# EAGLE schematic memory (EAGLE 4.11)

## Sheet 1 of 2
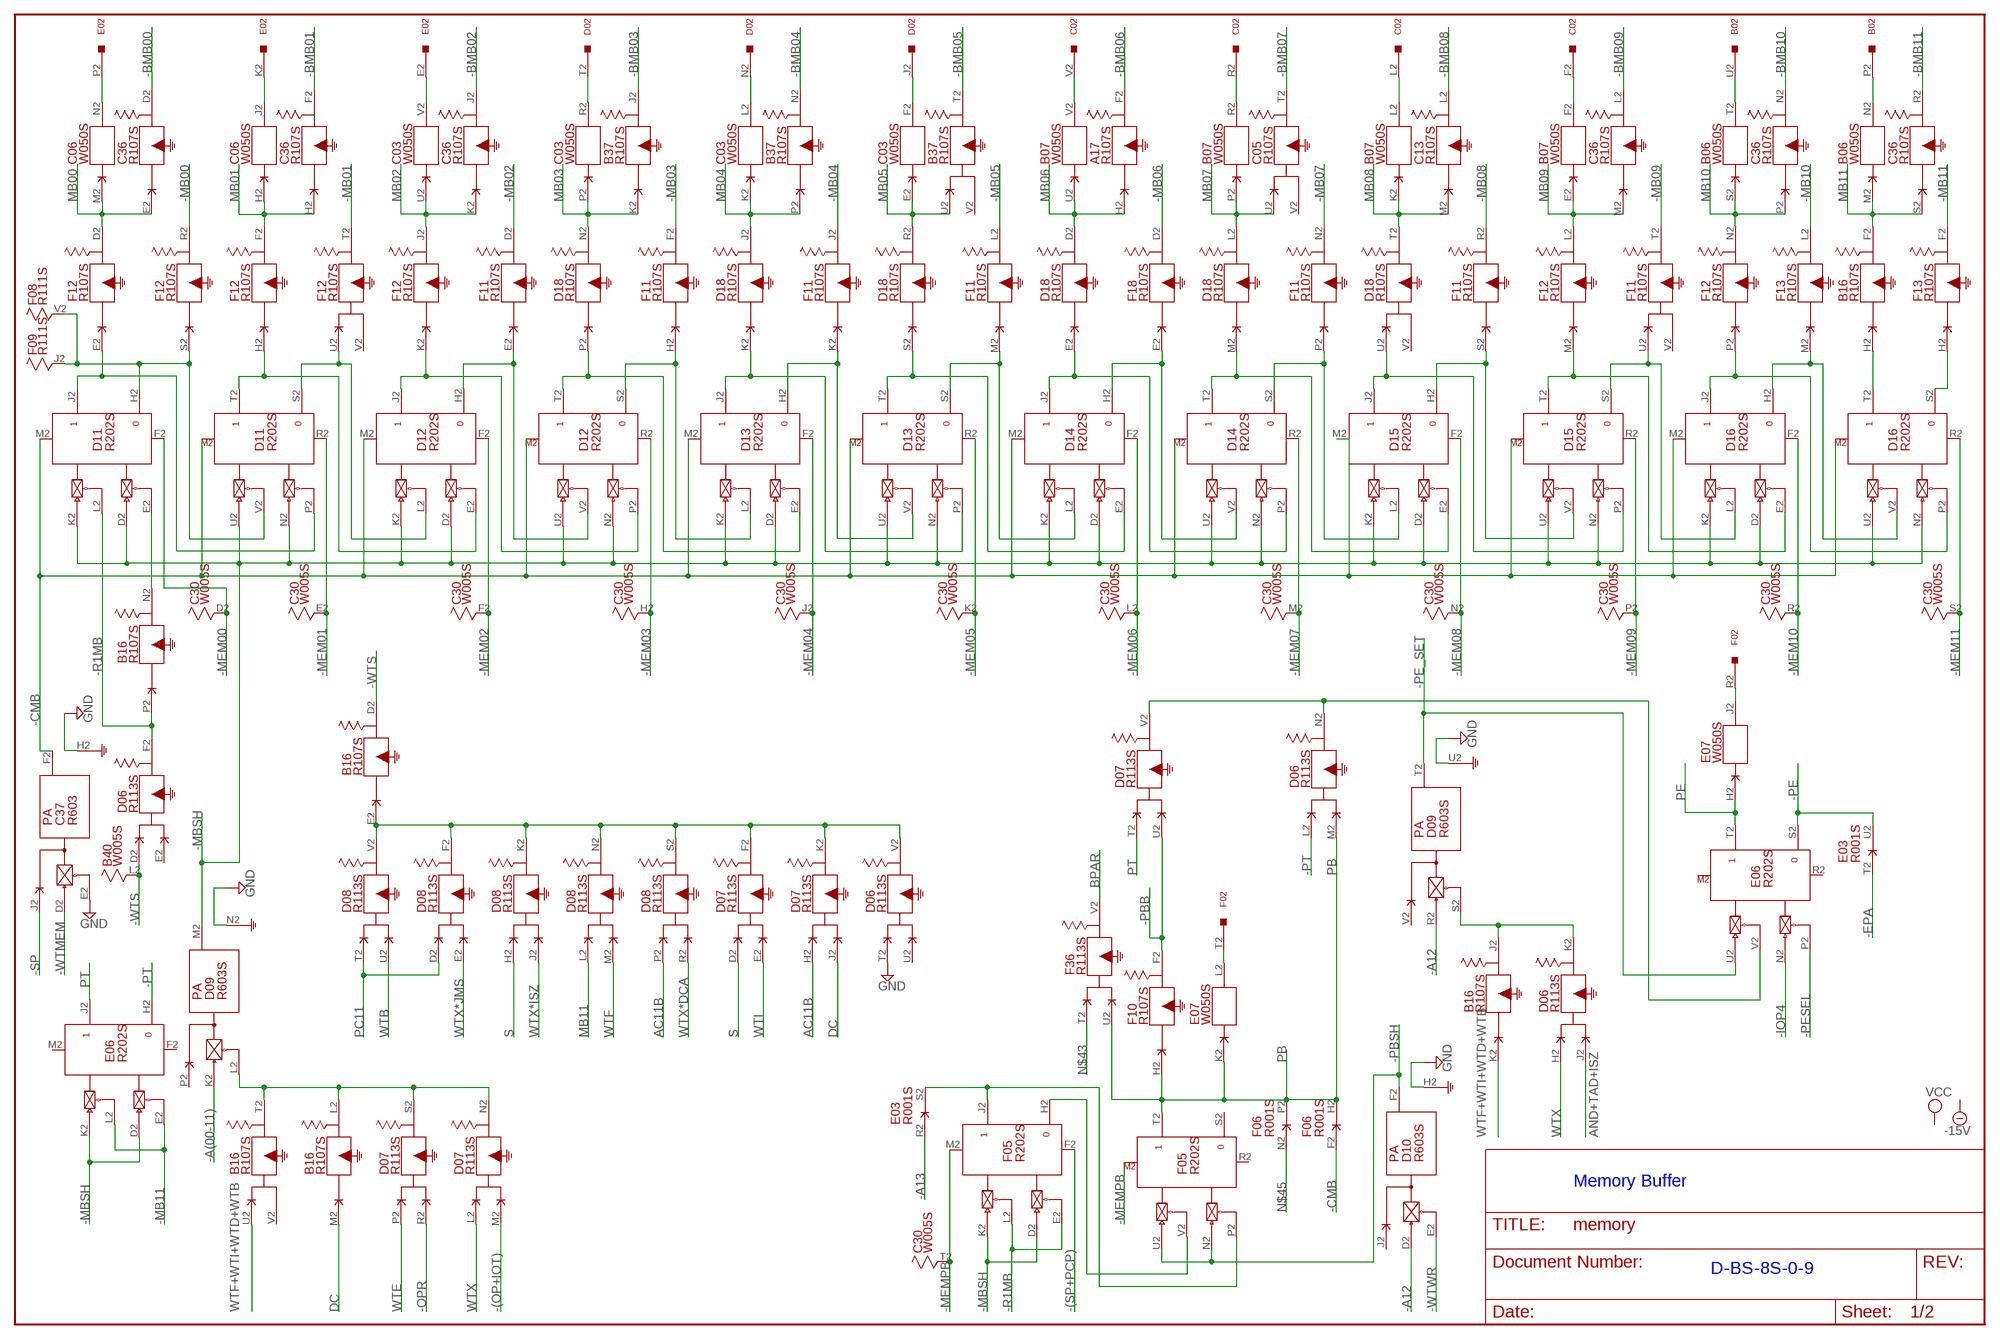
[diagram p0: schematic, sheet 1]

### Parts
A17  R107S  [H807S]
B02  W023S  [H807S]
B06  W050S  [H807S]
B07  W050S  [H807S]
B16  R107S  [H807S]
B37  R107S  [H807S]
B40  W005S  [H807S]
C02  W023S  [H807S]
C03  W050S  [H807S]
C05  R107S  [H807S]
C06  W050S  [H807S]
C13  R107S  [H807S]
C30  W005S  [H807S]
C36  R107S  [H807S]
C37  R603  [H807]
D02  W023S  [H807S]
D06  R113S  [H807S]
D07  R113S  [H807S]
D08  R113S  [H807S]
D09  R603S  [H807S]
D10  R603S  [H807S]
D11  R202S  [H807S]
D12  R202S  [H807S]
D13  R202S  [H807S]
D14  R202S  [H807S]
D15  R202S  [H807S]
D16  R202S  [H807S]
D18  R107S  [H807S]
E02  W023S  [H807S]
E03  R001S  [H807S]
E06  R202S  [H807S]
E07  W050S  [H807S]
F02  W023S  [H807S]
F05  R202S  [H807S]
F06  R001S  [H807S]
F08  R111S  [H807S]
F09  R111S  [H807S]
F10  R107S  [H807S]
F11  R107S  [H807S]
F12  R107S  [H807S]
F13  R107S  [H807S]
F18  R107S  [H807S]
F36  R113S  [H807S]

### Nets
-(OP+IOT): D07.M2(N:I$2)
-(SP+PCP): F05.F2(J:RESET)
-A12: D09.R2(T:PU0) D10.D2(F:PU0)
-A13: E03.R2(S:D)
-A(00-11): D09.K2(M:PU0)
-BMB00: C36.D2(D:O$1)
-BMB01: C36.F2(F:O$1)
-BMB02: C36.J2(J:O$1)
-BMB03: B37.J2(J:O$1)
-BMB04: B37.N2(N:O$1)
-BMB05: B37.T2(T:O$1)
-BMB06: A17.F2(F:O$1)
-BMB07: C05.T2(T:O$1)
-BMB08: C13.L2(L:O$1)
-BMB09: C36.L2(L:O$1)
-BMB10: C36.N2(N:O$1)
-BMB11: C36.R2(R:O$1)
-CMB: C37.F2(F:O) D11.M2(J:SET) D12.M2(J:SET) D13.M2(J:SET) D14.M2(J:SET) D15.M2(J:SET) D16.M2(J:SET) F06.F2(H:D)
-EPA: E03.T2(U:D)
-IOP4: E06.N2(T:PU0)
-MB00: F12.R2(R:O$1) ; also sheet 2
-MB01: F12.T2(T:O$1) ; also sheet 2
-MB02: F11.D2(D:O$1) ; also sheet 2
-MB03: F11.F2(F:O$1) ; also sheet 2
-MB04: F11.J2(J:O$1) ; also sheet 2
-MB05: F11.L2(L:O$1) ; also sheet 2
-MB06: F18.D2(D:O$1) ; also sheet 2
-MB07: F11.N2(N:O$1) ; also sheet 2
-MB08: F11.R2(R:O$1) ; also sheet 2
-MB09: F11.T2(T:O$1) ; also sheet 2
-MB10: F13.L2(L:O$1) ; also sheet 2
-MB11: E06.E2(J:EN0) E06.L2(J:EN1) F13.F2(F:O$1) ; also sheet 2
-MBSH: D09.M2(M:O) D11.D2(J:PU0) D11.K2(J:PU1) D11.N2(T:PU0) D11.U2(T:PU1) D12.D2(J:PU0) D12.K2(J:PU1) D12.N2(T:PU0) D12.U2(T:PU1) D13.D2(J:PU0) D13.K2(J:PU1) D13.N2(T:PU0) D13.U2(T:PU1) D14.D2(J:PU0) D14.K2(J:PU1) D14.N2(T:PU0) D14.U2(T:PU1) D15.D2(J:PU0) D15.K2(J:PU1) D15.N2(T:PU0) D15.U2(T:PU1) D16.D2(J:PU0) D16.K2(J:PU1) D16.N2(T:PU0) D16.U2(T:PU1) E06.D2(J:PU0) E06.K2(J:PU1) F05.D2(J:PU0) F05.K2(J:PU1)
-MEM00: C30.D2 D11.F2(J:RESET) ; also sheet 2
-MEM01: C30.E2 D11.R2(T:RESET) ; also sheet 2
-MEM02: C30.F2 D12.F2(J:RESET) ; also sheet 2
-MEM03: C30.H2 D12.R2(T:RESET) ; also sheet 2
-MEM04: C30.J2 D13.F2(J:RESET) ; also sheet 2
-MEM05: C30.K2 D13.R2(T:RESET) ; also sheet 2
-MEM06: C30.L2 D14.F2(J:RESET) ; also sheet 2
-MEM07: C30.M2 D14.R2(T:RESET) ; also sheet 2
-MEM08: C30.N2 D15.F2(J:RESET) ; also sheet 2
-MEM09: C30.P2 D15.R2(T:RESET) ; also sheet 2
-MEM10: C30.R2 D16.F2(J:RESET) ; also sheet 2
-MEM11: C30.S2 D16.R2(T:RESET) ; also sheet 2
-MEMPB: C30.T2 F05.M2(J:SET) ; also sheet 2
-OPR: D07.R2(S:I$2)
-PBB: D07.U2(V:I$2) F10.F2(F:O$1) ; also sheet 2
-PBSH: D10.F2(F:O) F05.N2(T:PU0) F05.U2(T:PU1)
-PE: E03.U2(U:E) E06.S2
-PE_SET: D09.T2(T:O) E06.U2(T:PU1)
-PESEL: E06.P2(T:EN0)
-PT: D06.L2(N:I$1) E06.H2
-R1MB: B16.P2(N:I$1) D06.F2(F:O$1) D11.L2(J:EN1) F05.E2(J:EN0) F05.L2(J:EN1)
-SP: C37.J2(F:I$1)
-WTMEM: C37.D2(F:PU0)
-WTS: B16.D2(D:O$1) B40.L2 D06.D2(F:I$1)
-WTWR: D10.E2(F:EN0)
AC11B: D07.H2(K:I$1) D08.P2(S:I$1)
AND+TAD+ISZ: D06.J2(K:I$2)
BPAR: F36.V2(V:O$1)
DC: B16.M2(L:I$1) D07.J2(K:I$2)
GND [Supply]: C37.E2(F:EN0) C37.H2(F:G) D06.T2(V:I$1) D09.N2(M:G) D09.U2(T:G) D10.H2(F:G) ; also sheet 2
MB00: C06.M2(N:I$1) C36.E2(D:I$1) F12.D2(D:O$1)
MB01: C06.H2(J:I$1) C36.H2(F:I$1) F12.F2(F:O$1)
MB02: C03.U2(V:I$1) C36.K2(J:I$1) F12.J2(J:O$1)
MB03: B37.K2(J:I$1) C03.P2(R:I$1) D18.N2(N:O$1)
MB04: B37.P2(N:I$1) C03.K2(L:I$1) D18.J2(J:O$1)
MB05: B37.U2(T:I$1) C03.E2(F:I$1) D18.R2(R:O$1)
MB06: A17.H2(F:I$1) B07.U2(V:I$1) D18.D2(D:O$1)
MB07: B07.P2(R:I$1) C05.U2(T:I$1) D18.L2(L:O$1)
MB08: B07.K2(L:I$1) C13.M2(L:I$1) D18.T2(T:O$1)
MB09: B07.E2(F:I$1) C36.M2(L:I$1) F12.L2(L:O$1)
MB10: B06.S2(T:I$1) C36.P2(N:I$1) F12.N2(N:O$1)
MB11: B06.M2(N:I$1) B16.F2(F:O$1) C36.S2(R:I$1) D08.L2(N:I$1)
N$1: D11.J2 D11.P2(T:EN0) F12.E2(D:I$1)
N$2: C06.N2(N:O$1) E02.P2
N$3: D11.H2 D11.V2(T:EN1) F08.V2 F09.J2 F12.S2(R:I$1)
N$4: D11.T2 D12.E2(J:EN0) F12.H2(F:I$1)
N$5: B16.E2(D:I$1) D06.V2(V:O$1) D07.F2(F:O$1) D07.K2(K:O$1) D08.F2(F:O$1) D08.K2(K:O$1) D08.N2(N:O$1) D08.S2(S:O$1) D08.V2(V:O$1)
N$6: D12.J2 D12.P2(T:EN0) F12.K2(J:I$1)
N$7: D12.T2 D13.E2(J:EN0) D18.P2(N:I$1)
N$8: D13.J2 D13.P2(T:EN0) D18.K2(J:I$1)
N$9: D13.T2 D14.E2(J:EN0) D18.S2(R:I$1)
N$10: D14.J2 D14.P2(T:EN0) D18.E2(D:I$1)
N$11: D14.T2 D15.E2(J:EN0) D18.M2(L:I$1)
N$12: D15.J2 D15.P2(T:EN0) D18.U2(T:I$1)
N$13: D15.H2 D15.V2(T:EN1) F11.S2(R:I$1)
N$14: D14.S2 D15.L2(J:EN1) F11.P2(N:I$1)
N$15: D14.H2 D14.V2(T:EN1) F18.E2(D:I$1)
N$16: D13.S2 D14.L2(J:EN1) F11.M2(L:I$1)
N$17: D15.T2 D16.E2(J:EN0) F12.M2(L:I$1)
N$18: D15.S2 D16.L2(J:EN1) F11.U2(T:I$1)
N$19: D16.J2 D16.P2(T:EN0) F12.P2(N:I$1)
N$20: D13.H2 D13.V2(T:EN1) F11.K2(J:I$1)
N$21: D12.S2 D13.L2(J:EN1) F11.H2(F:I$1)
N$22: D12.H2 D12.V2(T:EN1) F11.E2(D:I$1)
N$23: D11.S2 D12.L2(J:EN1) F12.U2(T:I$1)
N$24: D16.H2 D16.V2(T:EN1) F13.M2(L:I$1)
N$25: B16.H2(F:I$1) D16.T2
N$26: D16.S2 F13.H2(F:I$1)
N$27: C06.J2(J:O$1) E02.K2
N$28: C03.V2(V:O$1) E02.E2
N$29: C03.R2(R:O$1) D02.T2
N$30: C03.L2(L:O$1) D02.N2
N$31: C03.F2(F:O$1) D02.J2
N$32: B07.V2(V:O$1) C02.V2
N$33: B07.R2(R:O$1) C02.R2
N$34: B07.L2(L:O$1) C02.L2
N$35: B07.F2(F:O$1) C02.F2
N$36: B02.U2 B06.T2(T:O$1)
N$37: B02.P2 B06.N2(N:O$1)
N$38: B16.L2(L:O$1) B16.T2(T:O$1) D07.N2(N:O$1) D07.S2(S:O$1) D09.L2(M:EN0)
N$39: B16.N2(N:O$1) D11.E2(J:EN0)
N$40: B16.J2(J:O$1) D06.K2(K:O$1) D09.S2(T:EN0)
N$41: E07.J2(J:O$1) F02.R2
N$42: D06.N2(N:O$1) D07.V2(V:O$1) E06.V2(T:EN1)
N$43: F36.T2(V:I$1)
N$44: E07.L2(L:O$1) F02.T2
N$45: F06.N2(P:D)
N$46: F05.H2 F05.V2(T:EN1)
N$47: E03.S2(S:E) F05.J2 F05.P2(T:EN0)
PB: D06.M2(N:I$2) E07.K2(L:I$1) F05.T2 F06.H2(H:E) F06.P2(P:E) F10.H2(F:I$1) F36.U2(V:I$2)
PC11: D08.D2(F:I$1) D08.T2(V:I$1)
PE: E06.T2 E07.H2(J:I$1)
PT: D07.T2(V:I$1) E06.J2
S: D07.D2(F:I$1) D08.H2(K:I$1)
WTB: D08.U2(V:I$2)
WTE: D07.P2(S:I$1)
WTF: D08.M2(N:I$2)
WTF+WTI+WTD+WTB: B16.K2(J:I$1) B16.U2(T:I$1)
WTI: D07.E2(F:I$2)
WTX: D06.H2(K:I$1) D07.L2(N:I$1)
WTX*DCA: D08.R2(S:I$2)
WTX*ISZ: D08.J2(K:I$2)
WTX*JMS: D08.E2(F:I$2)
Unconnected: A17.D2(D:O$1) A17.E2(D:I$1) A17.J2(J:O$1) A17.K2(J:I$1) A17.L2(L:O$1) A17.M2(L:I$1) A17.N2(N:O$1) A17.P2(N:I$1) A17.R2(R:O$1) A17.S2(R:I$1) A17.T2(T:O$1) A17.U2(T:I$1) A17.V2(T:I$2) B02.A2 B02.B2 B02.C2 B02.D2 B02.E2 B02.F2 B02.H2 B02.J2 B02.K2 B02.L2 B02.M2 B02.N2 B02.R2 B02.S2 B02.T2 B02.V2 B06.E2(F:I$1) B06.F2(F:O$1) B06.H2(J:I$1) B06.J2(J:O$1) B06.K2(L:I$1) B06.L2(L:O$1) B06.P2(R:I$1) B06.R2(R:O$1) B06.U2(V:I$1) B06.V2(V:O$1) B07.H2(J:I$1) B07.J2(J:O$1) B07.M2(N:I$1) B07.N2(N:O$1) B07.S2(T:I$1) B07.T2(T:O$1) B16.R2(R:O$1) B16.S2(R:I$1) B16.V2(T:I$2) B37.D2(D:O$1) B37.E2(D:I$1) B37.F2(F:O$1) B37.H2(F:I$1) B37.L2(L:O$1) B37.M2(L:I$1) B37.R2(R:O$1) B37.S2(R:I$1) B37.V2(T:I$2) B40.D2 B40.E2 B40.F2 B40.H2 B40.J2 B40.K2 B40.M2 B40.N2 B40.P2 B40.R2 B40.S2 B40.T2 B40.U2 B40.V2 C02.A2 C02.B2 C02.C2 C02.D2 C02.E2 C02.H2 C02.J2 C02.K2 C02.M2 C02.N2 C02.P2 C02.S2 C02.T2 C02.U2 C03.H2(J:I$1) C03.J2(J:O$1) C03.M2(N:I$1) C03.N2(N:O$1) C03.S2(T:I$1) C03.T2(T:O$1) C05.D2(D:O$1) C05.E2(D:I$1) C05.F2(F:O$1) C05.H2(F:I$1) C05.J2(J:O$1) C05.K2(J:I$1) C05.L2(L:O$1) C05.M2(L:I$1) C05.N2(N:O$1) C05.P2(N:I$1) C05.R2(R:O$1) C05.S2(R:I$1) C05.V2(T:I$2) C06.E2(F:I$1) C06.F2(F:O$1) C06.K2(L:I$1) C06.L2(L:O$1) C06.P2(R:I$1) C06.R2(R:O$1) C06.S2(T:I$1) C06.T2(T:O$1) C06.U2(V:I$1) C06.V2(V:O$1) C13.D2(D:O$1) C13.E2(D:I$1) C13.F2(F:O$1) C13.H2(F:I$1) C13.J2(J:O$1) C13.K2(J:I$1) C13.N2(N:O$1) C13.P2(N:I$1) C13.R2(R:O$1) C13.S2(R:I$1) C13.T2(T:O$1) C13.U2(T:I$1) C13.V2(T:I$2) C30.U2 C30.V2 C36.T2(T:O$1) C36.U2(T:I$1) C36.V2(T:I$2) C37.K2(M:PU0) C37.L2(M:EN0) C37.M2(M:O) C37.N2(M:G) C37.P2(M:I$1) C37.R2(T:PU0) C37.S2(T:EN0) C37.T2(T:O) C37.U2(T:G) C37.V2(T:I$1) D02.A2 D02.B2 D02.C2 D02.D2 D02.E2 D02.F2 D02.H2 D02.K2 D02.L2 D02.M2 D02.P2 D02.R2 D02.S2 D02.U2 D02.V2 D06.E2(F:I$2) D06.P2(S:I$1) D06.R2(S:I$2) D06.S2(S:O$1) D06.U2(V:I$2) D09.D2(F:PU0) D09.E2(F:EN0) D09.F2(F:O) D09.H2(F:G) D09.J2(F:I$1) D09.P2(M:I$1) D09.V2(T:I$1) D10.J2(F:I$1) D10.K2(M:PU0) D10.L2(M:EN0) D10.M2(M:O) D10.N2(M:G) D10.P2(M:I$1) D10.R2(T:PU0) D10.S2(T:EN0) D10.T2(T:O) D10.U2(T:G) D10.V2(T:I$1) D18.F2(F:O$1) D18.H2(F:I$1) D18.V2(T:I$2) E02.A2 E02.B2 E02.C2 E02.D2 E02.F2 E02.H2 E02.J2 E02.L2 E02.M2 E02.N2 E02.R2 E02.S2 E02.T2 E02.U2 E02.V2 E03.D2(E:D) E03.E2(E:E) E03.F2(H:D) E03.H2(H:E) E03.J2(K:D) E03.K2(K:E) E03.L2(M:D) E03.M2(M:E) E03.N2(P:D) E03.P2(P:E) E06.F2(J:RESET) E06.M2(J:SET) E06.R2(T:RESET) E07.E2(F:I$1) E07.F2(F:O$1) E07.M2(N:I$1) E07.N2(N:O$1) E07.P2(R:I$1) E07.R2(R:O$1) E07.S2(T:I$1) E07.T2(T:O$1) E07.U2(V:I$1) E07.V2(V:O$1) F02.A2 F02.B2 F02.C2 F02.D2 F02.E2 F02.F2 F02.H2 F02.J2 F02.K2 F02.L2 F02.M2 F02.N2 F02.P2 F02.S2 F02.U2 F02.V2 F05.R2(T:RESET) F05.S2 F06.D2(E:D) F06.E2(E:E) F06.J2(K:D) F06.K2(K:E) F06.L2(M:D) F06.M2(M:E) F06.R2(S:D) F06.S2(S:E) F06.T2(U:D) F06.U2(U:E) F08.D2(H:I$1) F08.E2(H:I$2) F08.F2(H:I$3) F08.H2(H:O$1) F08.J2 F08.K2(N:I$1) F08.L2(N:I$2) F08.M2(N:I$3) F08.N2(N:O$1) F08.P2 F08.R2(U:I$1) F08.S2(U:I$2) F08.T2(U:I$3) F08.U2(U:O$1) F09.D2(H:I$1) F09.E2(H:I$2) F09.F2(H:I$3) F09.H2(H:O$1) F09.K2(N:I$1) F09.L2(N:I$2) F09.M2(N:I$3) F09.N2(N:O$1) F09.P2 F09.R2(U:I$1) F09.S2(U:I$2) F09.T2(U:I$3) F09.U2(U:O$1) F09.V2 F10.D2(D:O$1) F10.E2(D:I$1) F10.J2(J:O$1) F10.K2(J:I$1) F10.L2(L:O$1) F10.M2(L:I$1) F10.N2(N:O$1) F10.P2(N:I$1) F10.R2(R:O$1) F10.S2(R:I$1) F10.T2(T:O$1) F10.U2(T:I$1) F10.V2(T:I$2) F11.V2(T:I$2) F12.V2(T:I$2) F13.D2(D:O$1) F13.E2(D:I$1) F13.J2(J:O$1) F13.K2(J:I$1) F13.N2(N:O$1) F13.P2(N:I$1) F13.R2(R:O$1) F13.S2(R:I$1) F13.T2(T:O$1) F13.U2(T:I$1) F13.V2(T:I$2) F18.F2(F:O$1) F18.H2(F:I$1) F18.J2(J:O$1) F18.K2(J:I$1) F18.L2(L:O$1) F18.M2(L:I$1) F18.N2(N:O$1) F18.P2(N:I$1) F18.R2(R:O$1) F18.S2(R:I$1) F18.T2(T:O$1) F18.U2(T:I$1) F18.V2(T:I$2) F36.D2(F:I$1) F36.E2(F:I$2) F36.F2(F:O$1) F36.H2(K:I$1) F36.J2(K:I$2) F36.K2(K:O$1) F36.L2(N:I$1) F36.M2(N:I$2) F36.N2(N:O$1) F36.P2(S:I$1) F36.R2(S:I$2) F36.S2(S:O$1)

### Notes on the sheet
- Memory Buffer
- D-BS-8S-0-9

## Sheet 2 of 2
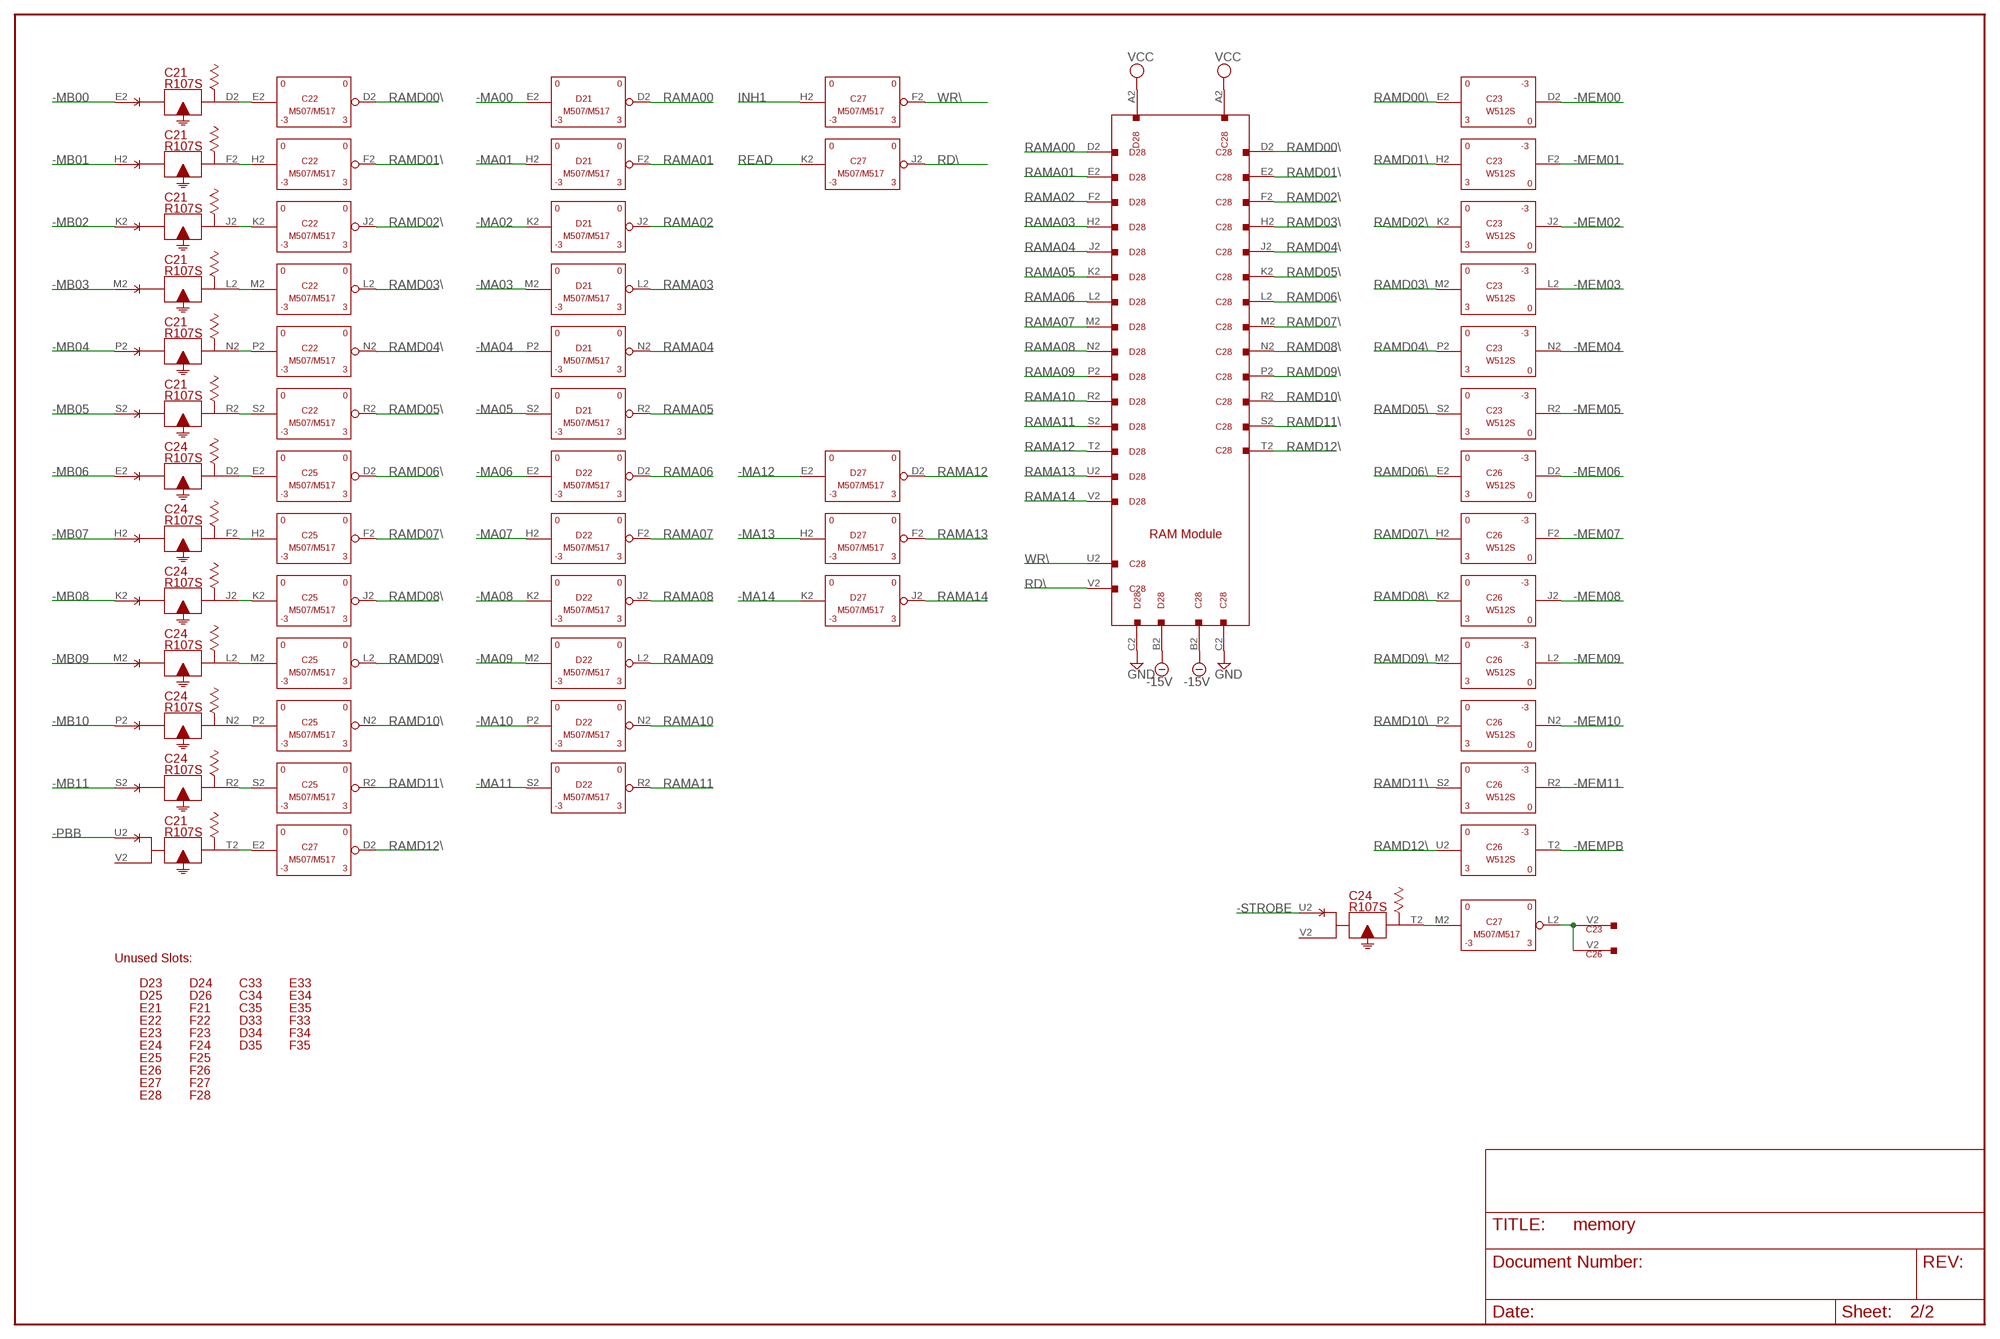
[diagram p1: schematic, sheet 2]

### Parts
C21  R107S  [H807S]
C22  M507S  [H807S]
C23  W512S  [H807S]
C24  R107S  [H807S]
C25  M507S  [H807S]
C26  W512S  [H807S]
C27  M507S  [H807S]
C28  W023S  [H807S]
C33  EMPTYS  [H807S]
C34  EMPTYS  [H807S]
C35  EMPTYS  [H807S]
D21  M507S  [H807S]
D22  M507S  [H807S]
D23  EMPTYS  [H807S]
D24  EMPTYS  [H807S]
D25  EMPTYS  [H807S]
D26  EMPTYS  [H807S]
D27  M507S  [H807S]
D28  W023S  [H807S]
D33  EMPTYS  [H807S]
D34  EMPTYS  [H807S]
D35  EMPTYS  [H807S]
E21  EMPTYS  [H807S]
E22  EMPTYS  [H807S]
E23  EMPTYS  [H807S]
E24  EMPTYS  [H807S]
E25  EMPTYS  [H807S]
E26  EMPTYS  [H807S]
E27  EMPTYS  [H807S]
E28  EMPTYS  [H807S]
E33  EMPTYS  [H807S]
E34  EMPTYS  [H807S]
E35  EMPTYS  [H807S]
F21  EMPTYS  [H807S]
F22  EMPTYS  [H807S]
F23  EMPTYS  [H807S]
F24  EMPTYS  [H807S]
F25  EMPTYS  [H807S]
F26  EMPTYS  [H807S]
F27  EMPTYS  [H807S]
F28  EMPTYS  [H807S]
F33  EMPTYS  [H807S]
F34  EMPTYS  [H807S]
F35  EMPTYS  [H807S]

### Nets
-15V [Supply]: C28.B2 D28.B2
-MA00: D21.E2(D:IN)
-MA01: D21.H2(F:IN)
-MA02: D21.K2(J:IN)
-MA03: D21.M2(L:IN)
-MA04: D21.P2(N:IN)
-MA05: D21.S2(R:IN)
-MA06: D22.E2(D:IN)
-MA07: D22.H2(F:IN)
-MA08: D22.K2(J:IN)
-MA09: D22.M2(L:IN)
-MA10: D22.P2(N:IN)
-MA11: D22.S2(R:IN)
-MA12: D27.E2(D:IN)
-MA13: D27.H2(F:IN)
-MA14: D27.K2(J:IN)
-MB00: C21.E2(D:I$1) ; also sheet 1
-MB01: C21.H2(F:I$1) ; also sheet 1
-MB02: C21.K2(J:I$1) ; also sheet 1
-MB03: C21.M2(L:I$1) ; also sheet 1
-MB04: C21.P2(N:I$1) ; also sheet 1
-MB05: C21.S2(R:I$1) ; also sheet 1
-MB06: C24.E2(D:I$1) ; also sheet 1
-MB07: C24.H2(F:I$1) ; also sheet 1
-MB08: C24.K2(J:I$1) ; also sheet 1
-MB09: C24.M2(L:I$1) ; also sheet 1
-MB10: C24.P2(N:I$1) ; also sheet 1
-MB11: C24.S2(R:I$1) ; also sheet 1
-MEM00: C23.D2(OUT) ; also sheet 1
-MEM01: C23.F2(OUT) ; also sheet 1
-MEM02: C23.J2(OUT) ; also sheet 1
-MEM03: C23.L2(OUT) ; also sheet 1
-MEM04: C23.N2(OUT) ; also sheet 1
-MEM05: C23.R2(OUT) ; also sheet 1
-MEM06: C26.D2(OUT) ; also sheet 1
-MEM07: C26.F2(OUT) ; also sheet 1
-MEM08: C26.J2(OUT) ; also sheet 1
-MEM09: C26.L2(OUT) ; also sheet 1
-MEM10: C26.N2(OUT) ; also sheet 1
-MEM11: C26.R2(OUT) ; also sheet 1
-MEMPB: C26.T2(OUT) ; also sheet 1
-PBB: C21.U2(T:I$1) ; also sheet 1
-STROBE: C24.U2(T:I$1)
GND [Supply]: C28.C2 D28.C2 ; also sheet 1
INH1: C27.H2(F:IN)
N$48: C24.T2(T:O$1) C27.M2(L:IN)
N$49: C24.D2(D:O$1) C25.E2(D:IN)
N$50: C21.R2(R:O$1) C22.S2(R:IN)
N$51: C21.N2(N:O$1) C22.P2(N:IN)
N$52: C21.L2(L:O$1) C22.M2(L:IN)
N$55: C21.J2(J:O$1) C22.K2(J:IN)
N$56: C21.F2(F:O$1) C22.H2(F:IN)
N$57: C21.D2(D:O$1) C22.E2(D:IN)
N$58: C24.F2(F:O$1) C25.H2(F:IN)
N$59: C24.J2(J:O$1) C25.K2(J:IN)
N$60: C24.L2(L:O$1) C25.M2(L:IN)
N$61: C24.N2(N:O$1) C25.P2(N:IN)
N$62: C24.R2(R:O$1) C25.S2(R:IN)
N$63: C21.T2(T:O$1) C27.E2(D:IN)
N$64: C23.V2 C26.V2 C27.L2(L:OUT)
RAMA00: D21.D2(D:OUT) D28.D2
RAMA01: D21.F2(F:OUT) D28.E2
RAMA02: D21.J2(J:OUT) D28.F2
RAMA03: D21.L2(L:OUT) D28.H2
RAMA04: D21.N2(N:OUT) D28.J2
RAMA05: D21.R2(R:OUT) D28.K2
RAMA06: D22.D2(D:OUT) D28.L2
RAMA07: D22.F2(F:OUT) D28.M2
RAMA08: D22.J2(J:OUT) D28.N2
RAMA09: D22.L2(L:OUT) D28.P2
RAMA10: D22.N2(N:OUT) D28.R2
RAMA11: D22.R2(R:OUT) D28.S2
RAMA12: D27.D2(D:OUT) D28.T2
RAMA13: D27.F2(F:OUT) D28.U2
RAMA14: D27.J2(J:OUT) D28.V2
RAMD00\: C22.D2(D:OUT) C23.E2(IN) C28.D2
RAMD01\: C22.F2(F:OUT) C23.H2(IN) C28.E2
RAMD02\: C22.J2(J:OUT) C23.K2(IN) C28.F2
RAMD03\: C22.L2(L:OUT) C23.M2(IN) C28.H2
RAMD04\: C22.N2(N:OUT) C23.P2(IN) C28.J2
RAMD05\: C22.R2(R:OUT) C23.S2(IN) C28.K2
RAMD06\: C25.D2(D:OUT) C26.E2(IN) C28.L2
RAMD07\: C25.F2(F:OUT) C26.H2(IN) C28.M2
RAMD08\: C25.J2(J:OUT) C26.K2(IN) C28.N2
RAMD09\: C25.L2(L:OUT) C26.M2(IN) C28.P2
RAMD10\: C25.N2(N:OUT) C26.P2(IN) C28.R2
RAMD11\: C25.R2(R:OUT) C26.S2(IN) C28.S2
RAMD12\: C26.U2(IN) C27.D2(D:OUT) C28.T2
RD\: C27.J2(J:OUT) C28.V2
READ: C27.K2(J:IN)
VCC [Supply]: C28.A2 D28.A2
WR\: C27.F2(F:OUT) C28.U2
Unconnected: C21.V2(T:I$2) C23.T2(OUT) C23.U2(IN) C24.V2(T:I$2) C27.N2(N:OUT) C27.P2(N:IN) C27.R2(R:OUT) C27.S2(R:IN) D27.L2(L:OUT) D27.M2(L:IN) D27.N2(N:OUT) D27.P2(N:IN) D27.R2(R:OUT) D27.S2(R:IN)

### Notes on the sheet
- RAM Module
- Unused Slots:

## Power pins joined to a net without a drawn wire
-15V: A17.B2(-15V) B06.B2(-15V) B07.B2(-15V) B16.B2(-15V) B37.B2(-15V) B40.B2(-15V) C03.B2(-15V) C05.B2(-15V) C06.B2(-15V) C13.B2(-15V) C21.B2(-15V) C22.B2(-15V) C23.B2(-15V) C24.B2(-15V) C25.B2(-15V) C26.B2(-15V) C27.B2(-15V) C30.B2(-15V) C33.B2 C34.B2 C35.B2 C36.B2(-15V) C37.B2(-15V) D06.B2(-15V) D07.B2(-15V) D08.B2(-15V) D09.B2(-15V) D10.B2(-15V) D11.B2(-15V) D12.B2(-15V) D13.B2(-15V) D14.B2(-15V) D15.B2(-15V) D16.B2(-15V) D18.B2(-15V) D21.B2(-15V) D22.B2(-15V) D23.B2 D24.B2 D25.B2 D26.B2 D27.B2(-15V) D33.B2 D34.B2 D35.B2 E03.B2(-15V) E06.B2(-15V) E07.B2(-15V) E21.B2 E22.B2 E23.B2 E24.B2 E25.B2 E26.B2 E27.B2 E28.B2 E33.B2 E34.B2 E35.B2 F05.B2(-15V) F06.B2(-15V) F08.B2(-15V) F09.B2(-15V) F10.B2(-15V) F11.B2(-15V) F12.B2(-15V) F13.B2(-15V) F18.B2(-15V) F21.B2 F22.B2 F23.B2 F24.B2 F25.B2 F26.B2 F27.B2 F28.B2 F33.B2 F34.B2 F35.B2 F36.B2(-15V)
GND: A17.C2(GND) B06.C2(GND) B07.C2(GND) B16.C2(GND) B37.C2(GND) B40.C2(GND) C03.C2(GND) C05.C2(GND) C06.C2(GND) C13.C2(GND) C21.C2(GND) C22.C2(GND) C23.C2(GND) C24.C2(GND) C25.C2(GND) C26.C2(GND) C27.C2(GND) C30.C2(GND) C33.C2 C34.C2 C35.C2 C36.C2(GND) C37.C2(GND) D06.C2(GND) D07.C2(GND) D08.C2(GND) D09.C2(GND) D10.C2(GND) D11.C2(GND) D12.C2(GND) D13.C2(GND) D14.C2(GND) D15.C2(GND) D16.C2(GND) D18.C2(GND) D21.C2(GND) D22.C2(GND) D23.C2 D24.C2 D25.C2 D26.C2 D27.C2(GND) D33.C2 D34.C2 D35.C2 E03.C2(GND) E06.C2(GND) E07.C2(GND) E21.C2 E22.C2 E23.C2 E24.C2 E25.C2 E26.C2 E27.C2 E28.C2 E33.C2 E34.C2 E35.C2 F05.C2(GND) F06.C2(GND) F08.C2(GND) F09.C2(GND) F10.C2(GND) F11.C2(GND) F12.C2(GND) F13.C2(GND) F18.C2(GND) F21.C2 F22.C2 F23.C2 F24.C2 F25.C2 F26.C2 F27.C2 F28.C2 F33.C2 F34.C2 F35.C2 F36.C2(GND)
VCC: A17.A2(VCC) B06.A2(VCC) B07.A2(VCC) B16.A2(VCC) B37.A2(VCC) B40.A2(VCC) C03.A2(VCC) C05.A2(VCC) C06.A2(VCC) C13.A2(VCC) C21.A2(VCC) C22.A2(VCC) C23.A2(VCC) C24.A2(VCC) C25.A2(VCC) C26.A2(VCC) C27.A2(VCC) C30.A2(VCC) C33.A2 C34.A2 C35.A2 C36.A2(VCC) C37.A2(VCC) D06.A2(VCC) D07.A2(VCC) D08.A2(VCC) D09.A2(VCC) D10.A2(VCC) D11.A2(VCC) D12.A2(VCC) D13.A2(VCC) D14.A2(VCC) D15.A2(VCC) D16.A2(VCC) D18.A2(VCC) D21.A2(VCC) D22.A2(VCC) D23.A2 D24.A2 D25.A2 D26.A2 D27.A2(VCC) D33.A2 D34.A2 D35.A2 E03.A2(VCC) E06.A2(VCC) E07.A2(VCC) E21.A2 E22.A2 E23.A2 E24.A2 E25.A2 E26.A2 E27.A2 E28.A2 E33.A2 E34.A2 E35.A2 F05.A2(VCC) F06.A2(VCC) F08.A2(VCC) F09.A2(VCC) F10.A2(VCC) F11.A2(VCC) F12.A2(VCC) F13.A2(VCC) F18.A2(VCC) F21.A2 F22.A2 F23.A2 F24.A2 F25.A2 F26.A2 F27.A2 F28.A2 F33.A2 F34.A2 F35.A2 F36.A2(VCC)

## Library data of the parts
A17 B16 B37 C05 C13 C21 C24 C36 D18 F10-F13 F18 = dec-r:R107: 7 Inverters
B02 C02 C28 D02 D28 E02 F02 = dec-r:W023: One-sided 18 pin connector/cable.
B06 B07 C03 C06 E07 = dec-r:W050: Indicator Driver
B40 C30 = dec-r:W005: 15 Clamped Loads
C22 C25 C27 D21 D22 D27 = dec-r:M507: M507 Negative Bus Converter
C23 C26 = dec-r:W512: Positive Level Converter
C33-C35 D23-D26 D33-D35 E21-E28 E33-E35 F21-F28 F33-F35 = dec-r:EMPTY: Empty Slot
C37 D09 D10 = dec-r:R603: Triple Pulse Amplifier
D06-D08 F36 = dec-r:R113: Diode Gate
D11-D16 E06 F05 = dec-r:R202: Dual Flip-Flop
E03 F06 = dec-r:R001: 7 Diodes
F08 F09 = dec-r:R111: Diode Gate

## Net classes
1 Supply: width 0.635 mm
